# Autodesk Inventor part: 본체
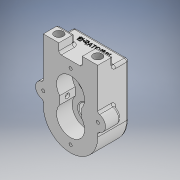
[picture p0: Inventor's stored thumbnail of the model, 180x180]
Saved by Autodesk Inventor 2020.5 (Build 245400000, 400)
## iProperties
Created: 2024-03
Part Number: 본체
Material: 일반
Document SubType Name: Modeling
Designer: 1강의실14
Density: 1 g/cm^3
Appearance: 기본값
Author: 1강의실14
## Parameters: d0 = 32 mm, d2 = 0, d3 = 33 mm, d7 = 35 mm, d9 = 0, d10 = 52 mm, d11 = 6 mm, d12 = 0, d13 = 12 mm, d16 = 0, d17 = 33 mm, d18 = 36 mm, d19 = 36 mm, d20 = 36 mm, d21 = 28 mm, d23 = 0, d25 = 63.5 mm, d27 = 0, d29 = 18 mm, d30 = 4 mm, d31 = 2 mm, d32 = 90 deg, d34 = 0, d35 = 14 mm, d37 = -60 deg, d38 = 15 mm, d39 = 18 mm, d40 = 4 mm, d41 = 2 mm, d42 = 90 deg, d44 = 0, d45 = 25 mm, d46 = 7.3 mm, d47 = 0, d48 = 15 mm, d49 = 63.5 mm, d50 = 8 mm, d51 = 6 mm, d52 = 0, d53 = 0, d54 = 10.5 mm, d55 = 11 mm, d56 = 0.62479 mm, d57 = 10.589 mm, d58 = 4 mm, d59 = 2 mm, d60 = 90 deg, d61 = 16 mm, d62 = 118 deg, d63 = 30 deg, d64 = 0.7 mm, d65 = 90 deg, d66 = 26 mm, d67 = 26 mm, d68 = 4.134 mm, d70 = 4 mm, d71 = 2 mm, d72 = 90 deg, d73 = 12 mm, d74 = 118 deg, d75 = 42 mm, d76 = 3.242 mm, d77 = 8 mm, d78 = 4 mm, d79 = 2 mm, d80 = 90 deg, d82 = 118 deg, d84 = 360 deg, d86 = 3 mm, d87 = 3 mm, d88 = 3 mm, d92 = 1 mm, d93 = 2 mm, d94 = 45 deg, d96 = 0.5 mm, d97 = 0, d98 = 1 mm, d99 = 2 mm, d100 = 45 deg
